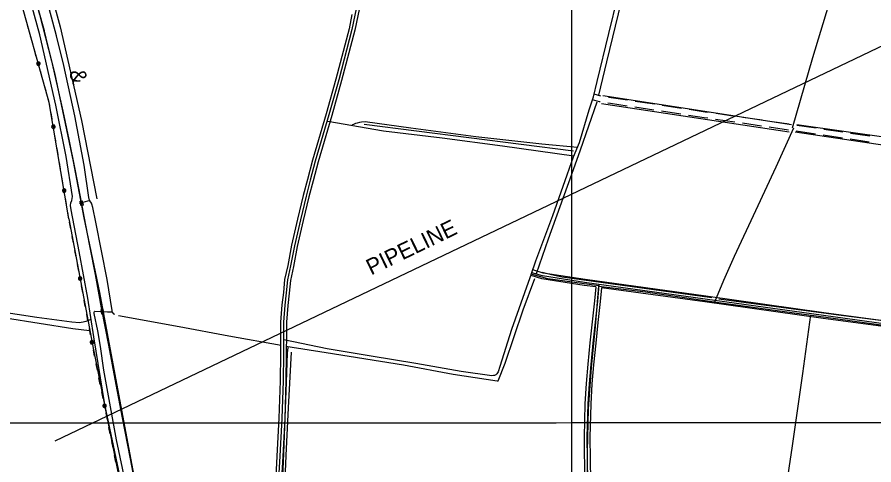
# Model space of a CAD drawing. Extents: x 3279314 to 3317160, y 734079 to 759431.
# Drawn here: x 3288472 to 3292879, y 745302 to 747608 of the extents above; entities that cross this region are included whole.
import ezdxf

# ---------------------------------------------------------------- set-up
doc = ezdxf.new("R2010")
doc.units = 0
for name, color, linetype in [('V-BRDG-OTLN', 7, 'Continuous'), ('V-DTCH-CNTR', 7, 'Continuous'), ('V-GRID-MAJR', 7, 'Continuous'), ('V-RAIL-IDEN', 7, 'Continuous'), ('V-RAIL-TRAK', 7, 'Continuous'), ('V-ROAD-CNTR', 7, 'Continuous'), ('V-TOPO-SHOR', 7, 'Continuous'), ('V-UTIL-IDEN', 7, 'Continuous'), ('V-UTIL-LINE', 7, 'Continuous')]:
    doc.layers.add(name, color=color, linetype=linetype)

msp = doc.modelspace()

# ---------------------------------------------------------------- linework, layer by layer
at = {"layer": 'V-BRDG-OTLN'}
for points in [[(3288801.2, 746636.8), (3288796.4, 746660), (3288806.3, 746662), (3288811, 746638.8)], [(3288907.7, 746078.2), (3288903.4, 746102.3), (3288912.3, 746104), (3288916.7, 746079.8)]]:
    msp.add_lwpolyline(points, close=True, dxfattribs=at)
at = {"layer": 'V-DTCH-CNTR'}
for points in [[(3288431.2, 748724.1), (3288382.5, 748706.8), (3288371.4, 748702.3), (3288362.7, 748697.4), (3288352.6, 748687.3), (3288348.3, 748675.9), (3288349.2, 748661.2), (3288352.1, 748649.5), (3288363.6, 748616.5), (3288430.7, 748445.3), (3288539.4, 748110.1), (3288633.9, 747774.2), (3288692.2, 747557.5), (3288802.7, 747075.2), (3288882.4, 746672.9)], [(3292461.1, 747038.6), (3292564.6, 747399.4), (3292647, 747671.7), (3292669.8, 747764.2), (3292695.6, 747888.1)], [(3289082.1, 744805.7), (3289048.6, 744993.3), (3288999.4, 745247), (3288923.3, 745613.3), (3288866, 745960.9), (3288836.1, 746160), (3288790.4, 746400.4), (3288750.1, 746614.7), (3288746.9, 746638.5), (3288748.4, 746652.1), (3288753.1, 746664.1), (3288755.4, 746673.8), (3288755.8, 746684.5), (3288724.6, 746890.6), (3288671.5, 747153.9), (3288589.1, 747517.4), (3288515, 747786.8)], [(3291116.2, 746283.1), (3291140.7, 746353.5), (3291228.1, 746586.4), (3291334.2, 746889), (3291364.3, 746962.9), (3291414.4, 747129.9), (3291436.4, 747196.9), (3291456.4, 747276.7), (3291515.1, 747524.2), (3291561.3, 747714.1)], [(3290069.3, 747072.5), (3290357.2, 747022.9), (3290658.1, 746985.6), (3290969, 746944.4), (3291336.2, 746894.1)], [(3291353.8, 746937.2), (3291170.4, 746954.5), (3290832.1, 746992.2), (3290497.9, 747035.9), (3290262.8, 747069.6), (3290244.2, 747067.6), (3290233.4, 747065.4), (3290221.2, 747062.1), (3290212.9, 747059.8), (3290205.4, 747056.6), (3290193.4, 747051.1)], [(3292062, 746141.4), (3292107.9, 746253.1), (3292162.5, 746376.4), (3292272, 746612.2), (3292376.7, 746836.9), (3292468.4, 747037.5)], [(3286480.4, 746311.6), (3286811.3, 746310.9), (3286914.8, 746304), (3287253.1, 746253.4), (3287508.8, 746215.3), (3287758.9, 746179.4), (3288058.1, 746139.3), (3288289.4, 746105.1), (3288573.6, 746062.7), (3288753.5, 746038), (3288792.4, 746035.4), (3288800.5, 746036.7), (3288810.6, 746038.4), (3288817.7, 746040), (3288826.1, 746042.7), (3288852.1, 746053.1)], [(3291407.7, 745070.2), (3291406.7, 745369.9), (3291410.7, 745591), (3291426.7, 745804.1), (3291446.4, 746013.8), (3291464.4, 746223.2), (3291201.8, 746260.1), (3291116.3, 746283.5), (3291100.1, 746241.9), (3291015.8, 745998.2), (3290955.8, 745807.8), (3290945.8, 745780.6), (3290942.3, 745775.2), (3290938.9, 745771), (3290934.6, 745765.9), (3290928.3, 745762.6), (3290923.1, 745761.8), (3290914, 745760.5), (3290755.3, 745782.4), (3290522.9, 745824.4), (3290293.8, 745861.1), (3290066.4, 745899), (3289843.3, 745945.1)], [(3291464.3, 746222.2), (3291703.7, 746193.6), (3292081.2, 746138.6), (3292631.9, 746063.4), (3293348.1, 745963.7), (3293631.4, 745920.6), (3293844.5, 745892.1), (3293865.5, 745886.6), (3293879.2, 745880.2), (3293886.3, 745874.9), (3293888.3, 745872.3), (3293893.3, 745864.5), (3293896.2, 745854.7), (3293897.6, 745847.5), (3293900.4, 745831.5), (3293871.2, 745605.1)], [(3292234.7, 743940.2), (3292273.1, 744183.1), (3292306.3, 744350.5), (3292337.9, 744575.1), (3292371.4, 744792.5), (3292414.4, 745089.1), (3292461.3, 745399.1), (3292513.4, 745772), (3292555.3, 746073.9)], [(3289803.3, 744924.5), (3289840.4, 744939.6), (3289847.4, 745142.8), (3289856.4, 745350.8), (3289868.4, 745596), (3289883.1, 745881.9)]]:
    msp.add_lwpolyline(points, dxfattribs=at)
at = {"layer": 'V-GRID-MAJR'}
for points in [[(3291328, 739459.9), (3291326.2, 745519.1), (3291324.4, 751580.9), (3291322.7, 757642.8), (3291322.7, 757645.4)], [(3283456.6, 745517.7), (3286079.8, 745518), (3291326.2, 745519.1), (3296572.6, 745521), (3301819.1, 745523.7), (3307065.5, 745527.1), (3312312, 745531.3), (3314935.2, 745533.7)]]:
    msp.add_spline(points, degree=3, dxfattribs=at)
at = {"layer": 'V-RAIL-TRAK'}
for points in [[(3288582.4, 747642.9), (3288610.2, 747538.7)], [(3289093.1, 745135.8), (3289091.5, 745144), (3289055.4, 745332.7), (3289014.3, 745544.1), (3288981.9, 745715.2), (3288943, 745918.8), (3288906.5, 746110.2), (3288874.2, 746282.1), (3288845.6, 746430.1), (3288816.6, 746581.9), (3288797.2, 746683.3), (3288770.1, 746824.4), (3288739.8, 746977.7), (3288709.1, 747124.1), (3288680.1, 747254.3), (3288648.1, 747390.2), (3288620.8, 747499.6), (3288610.2, 747538.7)]]:
    msp.add_lwpolyline(points, dxfattribs=at)
at = {"layer": 'V-ROAD-CNTR'}
for p, q in [((3291474.1, 747201.5), (3291440.6, 747211.3)), ((3291750.8, 747159), (3291652, 747174.1)), ((3291747.9, 747129.1), (3291649.1, 747144.2)), ((3291886.3, 747108), (3291787.5, 747123.1)), ((3291889.2, 747137.9), (3291790.4, 747153)), ((3292166.2, 747096.7), (3292067.2, 747111.1)), ((3292163.3, 747066.8), (3292064.3, 747081.2)), ((3292304.7, 747076.6), (3292205.8, 747091)), ((3292443.3, 747056.4), (3292344.3, 747070.8)), ((3292301.8, 747046.7), (3292202.9, 747061.1)), ((3292581.7, 747035.8), (3292482.8, 747050.5)), ((3292720.2, 747015.2), (3292621.3, 747029.9)), ((3292578.8, 747005.9), (3292479.9, 747020.7)), ((3292717.3, 746985.3), (3292618.4, 747000)), ((3292855.8, 746964.7), (3292756.9, 746979.4)), ((3292858.7, 746994.6), (3292759.8, 747009.3))]:
    msp.add_line(p, q, dxfattribs=at)
for points in [[(3287859.7, 749607.8), (3287996.9, 749316.5), (3288160.9, 748917.3), (3288374.4, 748331), (3288500.7, 747954.5), (3288586.6, 747621.7), (3288663.7, 747320.9), (3288760.6, 746864.5), (3288815, 746574.3)], [(3290231.5, 747726.6), (3290193.7, 747544.5), (3290126, 747285.2), (3290076.1, 747105.1), (3290005.2, 746867), (3289979.5, 746768.3), (3289958.4, 746685.7), (3289928.8, 746564.7), (3289898.3, 746430), (3289878.8, 746326.4), (3289862.5, 746254.4), (3289856.4, 746187.6), (3289849, 746124.1), (3289842.3, 746036.8), (3289841.4, 745871.2), (3289839.7, 745735), (3289833.8, 745541.2), (3289822.9, 745346.4), (3289813.3, 745173), (3289803, 744892.8), (3289785.9, 744579.1), (3289787, 744475.4), (3289799.7, 744409)], [(3290231.5, 747726.6), (3290193.7, 747544.5), (3290126, 747285.2), (3290076.1, 747105.1), (3290005.2, 746867), (3289979.5, 746768.3), (3289958.4, 746685.7), (3289928.8, 746564.7), (3289898.3, 746430), (3289878.8, 746326.4), (3289862.5, 746254.4), (3289856.4, 746187.6), (3289849, 746124.1), (3289842.3, 746036.8), (3289841.4, 745871.2), (3289839.7, 745735), (3289833.8, 745541.2), (3289822.9, 745346.4), (3289813.3, 745173), (3289803, 744892.8), (3289785.9, 744579.1), (3289787, 744475.4), (3289799.7, 744409)], [(3290246.2, 747723.5), (3290208.3, 747541.1), (3290140.5, 747281.3), (3290090.6, 747101), (3290019.7, 746863), (3289994, 746764.6), (3289972.9, 746682.1), (3289943.4, 746561.3), (3289913, 746427), (3289893.5, 746323.4), (3289877.3, 746252.1), (3289871.3, 746186.1), (3289864, 746122.7), (3289857.3, 746036.2), (3289857, 745980.8)], [(3290194.4, 747621.7), (3290179.1, 747548), (3290111.6, 747289.1), (3290061.7, 747109.2), (3289990.8, 746871), (3289965, 746772.1), (3289943.8, 746689.3), (3289914.2, 746568.2), (3289883.6, 746433.1), (3289864.1, 746329.5), (3289847.6, 746256.8), (3289841.5, 746189.2), (3289834.1, 746125.6), (3289827.3, 746037.4), (3289827, 745980.8)], [(3291471.2, 747171.4), (3291468, 747172), (3291432.2, 747182.5)], [(3291609.5, 747150.2), (3291524.4, 747163.2), (3291510.6, 747165)], [(3291612.4, 747180.1), (3291528.7, 747192.9), (3291513.5, 747194.9)], [(3292027.6, 747116.9), (3292011, 747119.3), (3291928.8, 747131.9)], [(3292024.7, 747087), (3292006.5, 747089.6), (3291925.9, 747102)], [(3292440.4, 747026.5), (3292439.9, 747026.6), (3292341.4, 747040.9)], [(3288815, 746574.3), (3288895.2, 746188.9), (3289013.4, 745556.4), (3289124.8, 744962), (3289225.5, 744441.7), (3289443.5, 743294.9), (3289638.7, 742286.7), (3289706.6, 741919.8), (3289751.6, 741687.2)], [(3291448.5, 746218), (3291388.9, 746226.2), (3291171.1, 746260.4), (3291116.1, 746277.2)], [(3293004.2, 746018.7), (3292620.2, 746070.6), (3292012.2, 746155.7), (3291391.1, 746241.1), (3291174.5, 746275), (3291120.4, 746291.5)], [(3293004.2, 746018.7), (3292620.2, 746070.6), (3292012.2, 746155.7), (3291391.1, 746241.1), (3291174.5, 746275), (3291120.4, 746291.5)], [(3293019.7, 746054.1), (3293017.9, 746043.5), (3293010.4, 746034.4), (3293004.5, 746033.8), (3292622.3, 746085.4), (3292014.2, 746170.6), (3291393.3, 746255.9), (3291177.8, 746289.7), (3291124.8, 746305.9)], [(3291464.8, 746230.9), (3291456.7, 746145.2), (3291445, 746037), (3291433.6, 745929.4), (3291422.9, 745819.1), (3291414.3, 745719.6), (3291407.9, 745615.5), (3291403.4, 745445), (3291406.3, 745218.5), (3291404.4, 745084.8), (3291405, 744975.6), (3291404.1, 744860.8), (3291405.4, 744787.1), (3291403.2, 744705.8), (3291403, 744625.4), (3291397.8, 744553.8), (3291389.8, 744488.5), (3291387.1, 744450.7)], [(3291464.8, 746230.9), (3291456.7, 746145.2), (3291445, 746037), (3291433.6, 745929.4), (3291422.9, 745819.1), (3291414.3, 745719.6), (3291407.9, 745615.5), (3291403.4, 745445), (3291406.3, 745218.5), (3291404.4, 745084.8), (3291405, 744975.6), (3291404.1, 744860.8), (3291405.4, 744787.1), (3291403.2, 744705.8), (3291403, 744625.4), (3291397.8, 744553.8), (3291389.8, 744488.5), (3291387.1, 744450.7)], [(3291448.5, 746218), (3291441.7, 746146.7), (3291430.1, 746038.6), (3291418.7, 745931), (3291408, 745820.5), (3291399.3, 745720.7), (3291392.9, 745616.1), (3291388.4, 745445.1), (3291391.3, 745218.5), (3291389.4, 745084.8), (3291390, 744975.6), (3291389.1, 744860.8), (3291390.4, 744787.2), (3291388.2, 744706), (3291388, 744625.9), (3291382.9, 744555.3), (3291374.8, 744489.9), (3291372.1, 744451.8)], [(3291478.3, 746214), (3291471.6, 746143.7), (3291459.9, 746035.4), (3291448.5, 745927.9), (3291437.8, 745817.7), (3291429.2, 745718.5), (3291422.9, 745614.8), (3291418.4, 745444.9), (3291421.3, 745218.5), (3291419.4, 745084.7), (3291420, 744975.6), (3291419.1, 744860.9), (3291420.4, 744787), (3291418.2, 744705.6), (3291418, 744624.8), (3291412.8, 744552.3), (3291404.7, 744487), (3291402.1, 744449.7)], [(3293046.8, 746033.9), (3293046.2, 746030.6), (3293025.6, 746005.7), (3293003.9, 746003.6), (3292618.2, 746055.7), (3292010.1, 746140.8), (3291478.3, 746214)], [(3289827, 745980.8), (3289826.4, 745871.4), (3289824.7, 745735.4), (3289818.8, 745541.9), (3289807.9, 745347.2), (3289798.4, 745173.7), (3289788, 744893.5), (3289770.9, 744579.4), (3289772, 744473.9), (3289782.2, 744420.9)], [(3289857, 745980.8), (3289856.4, 745871.1), (3289854.7, 745734.7), (3289848.8, 745540.6), (3289837.9, 745345.5), (3289828.3, 745172.3), (3289818, 744892.2), (3289800.9, 744578.8), (3289801.9, 744476.9), (3289811.8, 744425.6)]]:
    msp.add_lwpolyline(points, dxfattribs=at)
at = {"layer": 'V-TOPO-SHOR'}
for p, q in [((3292455.3, 747053.2), (3291485.6, 747202.5)), ((3291477.8, 747162.6), (3292443.4, 747017.3)), ((3290257.4, 747056), (3291334.7, 746918.9)), ((3292978, 746982.7), (3292483.2, 747053.3)), ((3292475.3, 747017.4), (3293153.7, 746915.3))]:
    msp.add_line(p, q, dxfattribs=at)
for points in [[(3291463.9, 747206.3), (3291504.9, 747378.6), (3291581.6, 747689.3), (3291623.4, 747865.1), (3291681.3, 748100)], [(3288845.1, 746663.7), (3288843, 746669.6), (3288841.3, 746678.5), (3288816.9, 746845.1), (3288768.8, 747100.5), (3288711.4, 747358.2), (3288674, 747511.7), (3288616.8, 747725.5)], [(3291143.1, 746287.1), (3291206, 746466.3), (3291325.5, 746798.9), (3291369.8, 746925.3), (3291456.3, 747172)], [(3288845.1, 746663.7), (3288809.9, 746653.5), (3288791.6, 746648)], [(3288958.9, 746089.9), (3288960, 746089.9), (3288960.9, 746097.1), (3288934.8, 746257.1), (3288876.5, 746552.8), (3288861.9, 746626.7), (3288856.8, 746644.2), (3288854.2, 746650.1), (3288845.9, 746661.4), (3288845.1, 746663.7)], [(3292046.5, 746162.7), (3291276.4, 746268.6), (3291220.5, 746280.4), (3291172.7, 746292.3)], [(3289853.3, 745912.6), (3290061.7, 745880.7), (3290459.1, 745817), (3290714.3, 745769.4), (3290941.5, 745733.9), (3290946, 745733.8), (3290982.3, 745825.7), (3291074.3, 746100.6), (3291135.1, 746261.9)], [(3293008.2, 746033.3), (3292696.9, 746072.5), (3292082.5, 746154.8)], [(3288015.4, 746117.5), (3288125.2, 746101.3), (3288412.3, 746058.5), (3288757.5, 746004.6), (3288844.5, 745994)], [(3289152.4, 744537.2), (3289148.9, 744565), (3289105.2, 744808.6), (3289061.7, 745028.9), (3289032.5, 745194.8), (3288983.2, 745430.5), (3288917.1, 745790.3), (3288900.9, 745910.6), (3288887.5, 745992.6), (3288868.8, 746081.7), (3288868.6, 746088.9), (3288869, 746091), (3288870.3, 746092.5), (3288872.2, 746093), (3288936.3, 746089.4), (3288958.9, 746089.9)], [(3288958.9, 746089.9), (3288967.6, 746079.2), (3288971.8, 746077.8)], [(3288993.8, 746070.6), (3289305, 746013.9), (3289560.4, 745966.9), (3289829.4, 745918.2)], [(3289825.6, 744947.3), (3289828.5, 745047.3), (3289831.6, 745072.3), (3289843.4, 745361.3), (3289858.1, 745726.9), (3289862.5, 745876.9), (3289865.5, 745906.6)]]:
    msp.add_lwpolyline(points, dxfattribs=at)
at = {"layer": 'V-UTIL-LINE'}
for points in [[(3288738.4, 746569.3), (3288636.9, 747168.8), (3288472.7, 747753.3), (3288305, 748308.9), (3288066.2, 748903.2), (3287813.4, 749483), (3287572, 750013.5), (3287250.9, 750510.8), (3286873.5, 750937.9), (3286412.5, 751389.7), (3286105.8, 751626.1), (3285807.9, 751895.5), (3285494.3, 752160.6), (3284875.4, 752907.1), (3284538.1, 753405.9), (3283938.7, 754373.8), (3283626.5, 754851.9)], [(3288668.1, 745426), (3296052.2, 748960.2), (3296218.4, 748982.8)], [(3288530.3, 747548.1), (3288521.1, 747580.9)], [(3288550.4, 747476.9), (3288541.2, 747509.6)], [(3288570.4, 747405.6), (3288561.2, 747438.4)], [(3288580.9, 747368.1), (3288579.1, 747365.9), (3288581.4, 747365.7), (3288583.1, 747367.8), (3288582, 747370.6), (3288578.7, 747369.8), (3288576.3, 747365.8), (3288579.1, 747362.5), (3288583.9, 747362.5), (3288586.4, 747366.4), (3288586.1, 747370.9), (3288582.2, 747373.6), (3288576.8, 747372.5), (3288572.3, 747365.7), (3288573.9, 747362.5), (3288576.5, 747360.2), (3288579.9, 747359.2), (3288583.4, 747359.4), (3288586.5, 747361), (3288588.8, 747363.7), (3288589.9, 747367), (3288589.6, 747370.5), (3288588, 747373.7), (3288585.3, 747375.9), (3288582, 747377), (3288578.5, 747376.8), (3288575.4, 747375.2), (3288573.1, 747372.5), (3288572, 747369.2), (3288572.3, 747365.7)], [(3288600.7, 747297.8), (3288591.5, 747330.5)], [(3288620.7, 747226.6), (3288611.5, 747259.3)], [(3288639.3, 747155), (3288636.9, 747168.8), (3288631.5, 747188.1)], [(3288651.6, 747082.1), (3288645.9, 747115.6)], [(3288658.1, 747043.6), (3288656.1, 747041.6), (3288658.4, 747041.2), (3288660.3, 747043.1), (3288659.5, 747045.9), (3288656.1, 747045.5), (3288653.3, 747041.8), (3288655.7, 747038.2), (3288660.5, 747037.8), (3288663.4, 747041.3), (3288663.6, 747045.8), (3288659.9, 747049), (3288654.5, 747048.4), (3288649.3, 747042.1), (3288650.5, 747038.8), (3288652.9, 747036.3), (3288656.1, 747034.8), (3288659.6, 747034.7), (3288662.9, 747036), (3288665.5, 747038.4), (3288666.9, 747041.6), (3288667, 747045.1), (3288665.8, 747048.4), (3288663.3, 747050.9), (3288660.1, 747052.4), (3288656.6, 747052.5), (3288653.3, 747051.2), (3288650.8, 747048.8), (3288649.4, 747045.6), (3288649.3, 747042.1)], [(3288670.3, 746971.6), (3288664.6, 747005.1)], [(3288682.7, 746898.7), (3288677, 746932.2)], [(3288695, 746825.7), (3288689.3, 746859.2)], [(3288707.4, 746752.7), (3288701.7, 746786.3)], [(3288713.9, 746714.3), (3288711.8, 746712.3), (3288714.1, 746711.8), (3288716, 746713.8), (3288715.2, 746716.6), (3288711.8, 746716.2), (3288709, 746712.5), (3288711.4, 746708.9), (3288716.3, 746708.4), (3288719.1, 746712), (3288719.3, 746716.5), (3288715.7, 746719.7), (3288710.2, 746719.1), (3288705, 746712.8), (3288706.3, 746709.5), (3288708.7, 746706.9), (3288711.9, 746705.5), (3288715.4, 746705.4), (3288718.7, 746706.7), (3288721.2, 746709.1), (3288722.7, 746712.3), (3288722.8, 746715.8), (3288721.5, 746719.1), (3288719.1, 746721.6), (3288715.9, 746723.1), (3288712.4, 746723.2), (3288709.1, 746721.9), (3288706.5, 746719.5), (3288705.1, 746716.3), (3288705, 746712.8)], [(3288726.1, 746642.3), (3288720.4, 746675.8)], [(3288738.4, 746569.3), (3288732.7, 746602.9)], [(3288738.4, 746569.3), (3288864, 745893.6), (3289082.5, 744800.2), (3289189.1, 744242.6), (3289413.2, 743060.2), (3289531, 742456.9), (3289644.5, 741853.6)], [(3288747.9, 746518.2), (3288741.7, 746551.6)], [(3288761.5, 746445.4), (3288755.2, 746478.8)], [(3288775, 746372.7), (3288768.8, 746406.1)], [(3288788.5, 746299.9), (3288782.3, 746333.3)], [(3288795.6, 746261.6), (3288793.6, 746259.5), (3288795.9, 746259.1), (3288797.8, 746261.1), (3288796.9, 746263.9), (3288793.6, 746263.5), (3288790.8, 746259.7), (3288793.3, 746256.2), (3288798.1, 746255.8), (3288800.9, 746259.4), (3288801, 746263.9), (3288797.3, 746267), (3288791.9, 746266.3), (3288786.8, 746259.9), (3288788.1, 746256.7), (3288790.5, 746254.2), (3288793.8, 746252.8), (3288797.3, 746252.7), (3288800.5, 746254), (3288803, 746256.5), (3288804.4, 746259.7), (3288804.5, 746263.2), (3288803.2, 746266.5), (3288800.7, 746269), (3288797.5, 746270.4), (3288794, 746270.4), (3288790.7, 746269.1), (3288788.2, 746266.7), (3288786.8, 746263.4), (3288786.8, 746259.9)], [(3288809, 746189.8), (3288802.8, 746223.2)], [(3288822.5, 746117.1), (3288816.3, 746150.5)], [(3288836, 746044.3), (3288829.8, 746077.7)], [(3288849.5, 745971.5), (3288843.3, 746005)], [(3288856.7, 745933.2), (3288854.6, 745931.2), (3288856.9, 745930.8), (3288858.8, 745932.8), (3288858, 745935.6), (3288854.6, 745935.1), (3288851.9, 745931.3), (3288854.3, 745927.8), (3288859.2, 745927.4), (3288861.9, 745931), (3288862.1, 745935.5), (3288858.4, 745938.6), (3288852.9, 745937.9), (3288847.8, 745931.6), (3288849.1, 745928.3), (3288851.6, 745925.8), (3288854.8, 745924.4), (3288858.3, 745924.4), (3288861.6, 745925.7), (3288864.1, 745928.1), (3288865.5, 745931.3), (3288865.5, 745934.8), (3288864.2, 745938.1), (3288861.8, 745940.6), (3288858.5, 745942), (3288855, 745942.1), (3288851.8, 745940.7), (3288849.2, 745938.3), (3288847.9, 745935.1), (3288847.8, 745931.6)], [(3288870.4, 745861.5), (3288864, 745893.6), (3288863.8, 745894.9)], [(3288884.9, 745789), (3288878.3, 745822.3)], [(3288899.4, 745716.4), (3288892.8, 745749.7)], [(3288913.9, 745643.8), (3288907.3, 745677.2)], [(3288921.6, 745605.6), (3288919.6, 745603.5), (3288921.9, 745603.1), (3288923.7, 745605.2), (3288922.8, 745608), (3288919.5, 745607.4), (3288916.8, 745603.6), (3288919.3, 745600.2), (3288924.1, 745599.8), (3288926.9, 745603.5), (3288927, 745608), (3288923.2, 745611), (3288917.8, 745610.2), (3288912.7, 745603.8), (3288914.1, 745600.6), (3288916.6, 745598.1), (3288919.8, 745596.7), (3288923.3, 745596.7), (3288926.6, 745598.1), (3288929.1, 745600.6), (3288930.4, 745603.8), (3288930.4, 745607.3), (3288929, 745610.6), (3288926.6, 745613.1), (3288923.3, 745614.4), (3288919.8, 745614.4), (3288916.6, 745613.1), (3288914.1, 745610.6), (3288912.7, 745607.3), (3288912.7, 745603.8)], [(3288935.9, 745534), (3288929.2, 745567.3)], [(3288950.4, 745461.4), (3288943.7, 745494.8)], [(3288964.9, 745388.9), (3288958.2, 745422.2)], [(3288979.4, 745316.3), (3288972.7, 745349.6)]]:
    msp.add_lwpolyline(points, dxfattribs=at)

# ---------------------------------------------------------------- texts
at = {"layer": 'V-RAIL-IDEN'}
msp.add_text('&', height=83, rotation=288.4347, dxfattribs=at).set_placement((3288736.7, 747325.2))
at = {"layer": 'V-UTIL-IDEN'}
msp.add_text('PIPELINE', height=83, rotation=25.8367, dxfattribs=at).set_placement((3290292.9, 746276.8))

doc.saveas('drawing.dxf')
